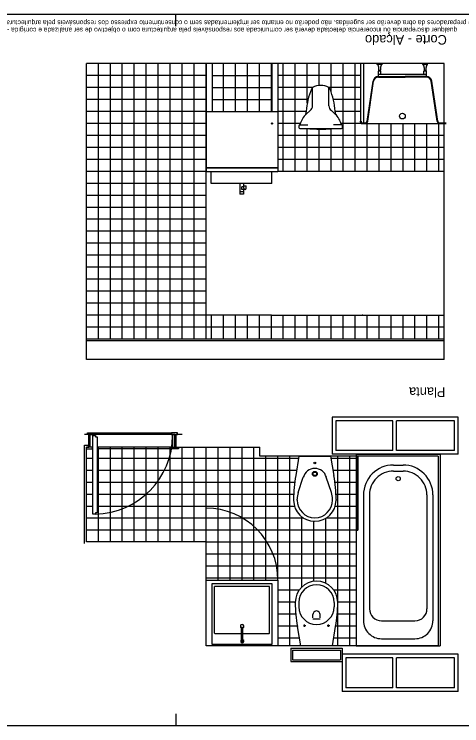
# Model space of a CAD drawing. Extents: x 1294.3 to 1305.9, y -284.7 to -278.8.
# Drawn here: x 1296.6 to 1300.34, y -284.72 to -278.78 of the extents above; entities that cross this region are included whole.
import ezdxf

# ---------------------------------------------------------------- set-up
doc = ezdxf.new("R2010")
doc.units = 0
for name, color, linetype in [('Level 1', 7, 'Continuous'), ('Level 10', 7, 'Continuous'), ('Level 11', 7, 'Continuous'), ('Level 13', 7, 'Continuous'), ('Level 2', 7, 'Continuous'), ('Level 36', 7, 'Continuous'), ('Level 4', 7, 'Continuous'), ('Level 60', 7, 'Continuous'), ('Level 62', 7, 'Continuous')]:
    doc.layers.add(name, color=color, linetype=linetype)

msp = doc.modelspace()

# ---------------------------------------------------------------- linework, layer by layer
at = {"layer": 'Level 1'}
for p, q in [((1297.206, -281.6585), (1297.206, -279.1885)), ((1300.196, -279.1885), (1297.206, -279.1885)), ((1299.496, -279.1885), (1299.496, -279.6685)), ((1299.521, -279.1885), (1299.521, -279.6835)), ((1300.196, -281.6585), (1300.196, -279.1885)), ((1299.496, -279.6685), (1299.501, -279.6685)), ((1299.501, -279.6685), (1299.501, -279.6735)), ((1299.511, -279.6835), (1299.521, -279.6835)), ((1300.196, -281.4885), (1297.206, -281.4885)), ((1300.196, -281.5035), (1297.206, -281.5035)), ((1300.196, -281.6585), (1297.206, -281.6585)), ((1300.311, -282.1396), (1299.2597, -282.1396)), ((1300.311, -282.4496), (1300.311, -282.1396)), ((1299.7653, -282.1696), (1299.2897, -282.1696)), ((1299.7653, -282.4196), (1299.7653, -282.1696)), ((1299.7953, -282.4196), (1299.7953, -282.1696)), ((1300.281, -282.1696), (1299.7953, -282.1696)), ((1300.281, -282.4196), (1300.281, -282.1696)), ((1297.226, -282.2846), (1297.191, -282.2846)), ((1297.226, -282.3896), (1297.226, -282.2846)), ((1298.006, -282.2846), (1297.956, -282.2846)), ((1297.956, -282.3896), (1297.956, -282.2846)), ((1297.191, -283.1946), (1297.191, -282.3746)), ((1297.191, -282.3746), (1297.226, -282.3746)), ((1297.206, -283.1796), (1297.206, -282.3896)), ((1297.206, -282.3896), (1297.226, -282.3896)), ((1297.956, -282.3896), (1298.656, -282.3896)), ((1298.656, -282.4646), (1298.656, -282.3896)), ((1299.7653, -282.4196), (1299.2897, -282.4196)), ((1300.281, -282.4196), (1299.7953, -282.4196)), ((1300.146, -282.4646), (1298.656, -282.4646)), ((1300.311, -282.4496), (1299.2597, -282.4496)), ((1300.311, -282.4496), (1299.2597, -282.4496)), ((1300.146, -282.4646), (1300.146, -284.0496)), ((1298.206, -283.1796), (1297.206, -283.1796)), ((1298.206, -284.0496), (1298.206, -283.1796)), ((1300.146, -284.0496), (1298.206, -284.0496)), ((1300.3122, -284.1196), (1299.3433, -284.1196)), ((1299.7665, -284.1496), (1299.3733, -284.1496)), ((1299.7665, -284.3996), (1299.7665, -284.1496)), ((1299.7965, -284.3996), (1299.7965, -284.1496)), ((1300.2822, -284.1496), (1299.7965, -284.1496)), ((1300.2822, -284.3996), (1300.2822, -284.1496)), ((1300.3122, -284.4296), (1300.3122, -284.1196)), ((1299.7665, -284.3996), (1299.3733, -284.3996)), ((1300.2822, -284.3996), (1299.7965, -284.3996)), ((1300.3122, -284.4296), (1299.3433, -284.4296))]:
    msp.add_line(p, q, dxfattribs=at)
for points in [[(1299.2597, -282.1396), (1299.2597, -282.4496)], [(1299.2897, -282.1696), (1299.2897, -282.4196)], [(1299.3433, -284.1196), (1299.3433, -284.4296)], [(1299.3733, -284.1496), (1299.3733, -284.3996)]]:
    msp.add_lwpolyline(points, dxfattribs=at)
msp.add_arc((1299.511, -279.6735), 0.01, 180, 270, dxfattribs=at)
at = {"layer": 'Level 10'}
for p, q in [((1297.306, -281.4885), (1297.306, -279.1885)), ((1297.406, -281.4885), (1297.406, -279.1885)), ((1297.506, -281.4885), (1297.506, -279.1885)), ((1297.606, -281.4885), (1297.606, -279.1885)), ((1297.706, -281.4885), (1297.706, -279.1885)), ((1297.806, -281.4885), (1297.806, -279.1885)), ((1297.906, -281.4885), (1297.906, -279.1885)), ((1298.006, -281.4885), (1298.006, -279.1885)), ((1298.106, -281.4885), (1298.106, -279.1885)), ((1298.351, -279.5885), (1298.351, -279.1885)), ((1298.451, -279.5885), (1298.451, -279.1885)), ((1298.551, -279.5885), (1298.551, -279.1885)), ((1298.651, -279.5885), (1298.651, -279.1885)), ((1298.751, -279.5885), (1298.751, -279.1885)), ((1298.806, -279.1885), (1298.806, -279.5885)), ((1298.851, -280.0885), (1298.851, -279.1885)), ((1298.951, -280.0885), (1298.951, -279.1885)), ((1299.051, -279.519), (1299.051, -279.1885)), ((1299.151, -279.3709), (1299.151, -279.1885)), ((1299.251, -279.4275), (1299.251, -279.1885)), ((1299.351, -280.0885), (1299.351, -279.1885)), ((1299.451, -280.0885), (1299.451, -279.1885)), ((1298.206, -279.2885), (1297.206, -279.2885)), ((1298.256, -279.2885), (1298.7558, -279.2885)), ((1299.496, -279.2885), (1298.8058, -279.2885)), ((1298.206, -279.3885), (1297.206, -279.3885)), ((1298.256, -279.3885), (1298.7558, -279.3885)), ((1299.0967, -279.3885), (1298.8058, -279.3885)), ((1299.496, -279.3885), (1299.2301, -279.3885)), ((1298.206, -279.4885), (1297.206, -279.4885)), ((1298.256, -279.4885), (1298.7558, -279.4885)), ((1299.0577, -279.4885), (1298.8058, -279.4885)), ((1299.496, -279.4885), (1299.2693, -279.4885)), ((1298.206, -279.5885), (1297.206, -279.5885)), ((1299.0415, -279.5885), (1298.8058, -279.5885)), ((1299.496, -279.5885), (1299.2856, -279.5885)), ((1298.206, -279.6885), (1297.206, -279.6885)), ((1298.9939, -279.6885), (1298.8058, -279.6885)), ((1299.506, -279.6885), (1299.3331, -279.6885)), ((1299.551, -280.0885), (1299.551, -279.6885)), ((1299.651, -280.0885), (1299.651, -279.6885)), ((1299.751, -280.0885), (1299.751, -279.6885)), ((1299.851, -280.0885), (1299.851, -279.6885)), ((1299.951, -280.0885), (1299.951, -279.6885)), ((1300.051, -280.0885), (1300.051, -279.6885)), ((1300.151, -280.0885), (1300.151, -279.6885)), ((1299.051, -280.0885), (1299.051, -279.7304)), ((1299.151, -280.0885), (1299.151, -279.7355)), ((1299.251, -280.0885), (1299.251, -279.7327)), ((1298.206, -279.7885), (1297.206, -279.7885)), ((1300.196, -279.7885), (1298.8058, -279.7885)), ((1298.206, -279.8885), (1297.206, -279.8885)), ((1300.196, -279.8885), (1298.8058, -279.8885)), ((1298.206, -279.9885), (1297.206, -279.9885)), ((1300.196, -279.9885), (1298.8058, -279.9885)), ((1298.206, -280.0885), (1297.206, -280.0885)), ((1298.206, -280.1885), (1297.206, -280.1885)), ((1298.206, -280.2885), (1297.206, -280.2885)), ((1298.206, -280.3885), (1297.206, -280.3885)), ((1298.206, -280.4885), (1297.206, -280.4885)), ((1298.206, -280.5885), (1297.206, -280.5885)), ((1298.206, -280.6885), (1297.206, -280.6885)), ((1298.206, -280.7885), (1297.206, -280.7885)), ((1298.206, -280.8885), (1297.206, -280.8885)), ((1298.206, -280.9885), (1297.206, -280.9885)), ((1298.206, -281.0885), (1297.206, -281.0885)), ((1298.206, -281.1885), (1297.206, -281.1885)), ((1298.206, -281.2885), (1297.206, -281.2885)), ((1298.251, -281.4885), (1298.251, -281.2885)), ((1298.351, -281.4885), (1298.351, -281.2885)), ((1298.451, -281.4885), (1298.451, -281.2885)), ((1298.551, -281.4885), (1298.551, -281.2885)), ((1298.651, -281.4885), (1298.651, -281.2885)), ((1298.751, -281.4885), (1298.751, -281.2885)), ((1298.751, -281.4885), (1298.751, -281.2885)), ((1298.851, -281.4885), (1298.851, -281.2885)), ((1298.951, -281.4885), (1298.951, -281.2885)), ((1299.051, -281.4885), (1299.051, -281.2885)), ((1299.151, -281.4885), (1299.151, -281.2885)), ((1299.251, -281.4885), (1299.251, -281.2885)), ((1299.351, -281.4885), (1299.351, -281.2885)), ((1299.451, -281.4885), (1299.451, -281.2885)), ((1299.551, -281.4885), (1299.551, -281.2885)), ((1299.651, -281.4885), (1299.651, -281.2885)), ((1299.751, -281.4885), (1299.751, -281.2885)), ((1299.851, -281.4885), (1299.851, -281.2885)), ((1299.951, -281.4885), (1299.951, -281.2885)), ((1300.051, -281.4885), (1300.051, -281.2885)), ((1300.151, -281.4885), (1300.151, -281.2885)), ((1300.196, -281.3885), (1297.206, -281.3885)), ((1297.916, -282.2846), (1297.266, -282.2846)), ((1297.926, -282.3896), (1297.296, -282.3896)), ((1297.306, -283.1796), (1297.306, -282.3896)), ((1297.406, -283.1796), (1297.406, -282.3896)), ((1297.506, -283.1796), (1297.506, -282.3896)), ((1297.606, -283.1796), (1297.606, -282.3896)), ((1297.706, -283.1796), (1297.706, -282.3896)), ((1297.806, -283.1796), (1297.806, -282.3896)), ((1297.906, -283.1796), (1297.906, -282.3896)), ((1298.006, -283.1796), (1298.006, -282.3896)), ((1298.106, -283.1796), (1298.106, -282.3896)), ((1298.206, -283.1796), (1298.206, -282.3896)), ((1298.306, -283.4996), (1298.306, -282.3896)), ((1298.406, -283.4996), (1298.406, -282.3896)), ((1298.506, -283.4996), (1298.506, -282.3896)), ((1298.606, -283.4996), (1298.606, -282.3896)), ((1297.261, -282.4846), (1297.206, -282.4846)), ((1298.9787, -282.4846), (1297.296, -282.4846)), ((1298.706, -283.4996), (1298.706, -282.4646)), ((1298.806, -283.4996), (1298.806, -282.4646)), ((1298.906, -284.0496), (1298.906, -282.4646)), ((1299.461, -282.4846), (1299.2499, -282.4846)), ((1299.306, -284.0496), (1299.306, -282.4646)), ((1299.406, -284.0496), (1299.406, -282.4646)), ((1297.261, -282.5846), (1297.206, -282.5846)), ((1298.9622, -282.5846), (1297.296, -282.5846)), ((1299.461, -282.5846), (1299.2663, -282.5846)), ((1297.261, -282.6846), (1297.206, -282.6846)), ((1298.9462, -282.6846), (1297.296, -282.6846)), ((1299.461, -282.6846), (1299.2824, -282.6846)), ((1297.261, -282.7846), (1297.206, -282.7846)), ((1298.9377, -282.7846), (1297.296, -282.7846)), ((1299.461, -282.7846), (1299.2909, -282.7846)), ((1297.261, -282.8846), (1297.206, -282.8846)), ((1298.9447, -282.8846), (1297.296, -282.8846)), ((1299.461, -282.8846), (1299.2838, -282.8846)), ((1299.006, -283.5586), (1299.006, -282.9727)), ((1299.0235, -282.9846), (1297.206, -282.9846)), ((1299.106, -283.511), (1299.106, -283.0094)), ((1299.461, -282.9846), (1299.2051, -282.9846)), ((1299.206, -283.5275), (1299.206, -282.9841)), ((1299.461, -283.0846), (1297.206, -283.0846)), ((1299.461, -283.1846), (1298.206, -283.1846)), ((1299.461, -283.2846), (1298.206, -283.2846)), ((1299.461, -283.3846), (1298.206, -283.3846)), ((1299.461, -283.4846), (1298.206, -283.4846)), ((1298.9851, -283.5846), (1298.806, -283.5846)), ((1299.461, -283.5846), (1299.2732, -283.5846)), ((1298.9508, -283.6846), (1298.806, -283.6846)), ((1299.461, -283.6846), (1299.3058, -283.6846)), ((1298.955, -283.7846), (1298.806, -283.7846)), ((1299.461, -283.7846), (1299.3016, -283.7846)), ((1298.9688, -283.8846), (1298.806, -283.8846)), ((1299.461, -283.8846), (1299.2878, -283.8846)), ((1298.9853, -283.9846), (1298.806, -283.9846)), ((1299.461, -283.9846), (1299.2713, -283.9846))]:
    msp.add_line(p, q, dxfattribs=at)
at = {"layer": 'Level 11'}
for p, q in [((1299.6765, -279.1884), (1299.6352, -279.1884)), ((1299.6352, -279.1951), (1299.6352, -279.1884)), ((1299.6765, -279.1951), (1299.6352, -279.1951)), ((1299.6765, -279.1951), (1299.6765, -279.1884)), ((1300.0567, -279.1884), (1300.0154, -279.1884)), ((1300.0154, -279.1951), (1300.0154, -279.1884)), ((1300.0567, -279.1951), (1300.0154, -279.1951)), ((1300.0567, -279.1951), (1300.0567, -279.1884)), ((1299.6454, -279.252), (1299.6503, -279.246)), ((1299.6664, -279.252), (1299.6454, -279.252)), ((1299.6454, -279.2965), (1299.6454, -279.252)), ((1300.0466, -279.2784), (1299.6454, -279.2784)), ((1299.6454, -279.2965), (1299.8217, -279.2965)), ((1299.6615, -279.246), (1299.6503, -279.246)), ((1299.6664, -279.252), (1299.6615, -279.246)), ((1299.6664, -279.2784), (1299.6664, -279.252)), ((1299.8217, -279.2965), (1299.8702, -279.2965)), ((1300.0466, -279.2965), (1299.8702, -279.2965)), ((1300.0256, -279.252), (1300.0305, -279.246)), ((1300.0466, -279.252), (1300.0256, -279.252)), ((1300.0256, -279.2784), (1300.0256, -279.252)), ((1300.0417, -279.246), (1300.0305, -279.246)), ((1300.0466, -279.252), (1300.0417, -279.246)), ((1300.0466, -279.2784), (1300.0466, -279.252)), ((1300.0466, -279.3012), (1300.0466, -279.2784)), ((1299.5509, -279.6707), (1299.6009, -279.3349)), ((1299.5561, -279.6701), (1299.6058, -279.3356)), ((1299.6454, -279.3015), (1299.8217, -279.3015)), ((1299.8217, -279.3015), (1299.8702, -279.3015)), ((1300.0466, -279.3015), (1299.8702, -279.3015)), ((1300.1361, -279.6701), (1300.0862, -279.3356)), ((1300.141, -279.6694), (1300.0911, -279.3348)), ((1299.096, -279.5404), (1299.096, -279.389)), ((1299.231, -279.5404), (1299.231, -279.389)), ((1299.0418, -279.5857), (1299.0375, -279.6144)), ((1299.0418, -279.6104), (1299.0746, -279.5802)), ((1299.2852, -279.6104), (1299.2524, -279.5802)), ((1299.2895, -279.6144), (1299.2852, -279.5857)), ((1298.981, -279.7078), (1298.981, -279.7224)), ((1298.9868, -279.7001), (1299.0561, -279.7001)), ((1299.3402, -279.7001), (1299.2709, -279.7001)), ((1299.346, -279.7224), (1299.346, -279.7078)), ((1299.496, -279.6685), (1299.501, -279.6685)), ((1299.496, -279.6785), (1299.496, -279.6685)), ((1299.501, -279.6785), (1299.501, -279.6685)), ((1299.506, -279.6835), (1299.5361, -279.6835)), ((1299.506, -279.6885), (1299.5361, -279.6885)), ((1299.5359, -279.6885), (1300.156, -279.6885)), ((1300.156, -279.6835), (1300.211, -279.6835)), ((1300.156, -279.6885), (1300.211, -279.6885)), ((1298.2494, -280.1885), (1298.2494, -280.0885)), ((1298.7538, -280.1885), (1298.7538, -280.0885)), ((1298.4889, -280.1885), (1298.4889, -280.2785)), ((1298.5189, -280.1885), (1298.5189, -280.2185)), ((1298.4889, -280.2385), (1298.4889, -280.2785)), ((1298.5189, -280.2385), (1298.5189, -280.2785)), ((1298.5215, -280.2285), (1298.5215, -280.2085)), ((1298.5215, -280.2085), (1298.5415, -280.2085)), ((1298.5415, -280.2285), (1298.5415, -280.2085)), ((1298.5189, -280.2585), (1298.4889, -280.2585)), ((1298.5189, -280.2785), (1298.4889, -280.2785)), ((1298.982, -282.4646), (1298.9553, -282.6266)), ((1298.982, -282.4646), (1299.2466, -282.4646)), ((1299.2466, -282.4646), (1299.2732, -282.6266)), ((1299.461, -282.4496), (1299.461, -284.0496)), ((1299.461, -282.4496), (1300.161, -282.4496)), ((1300.161, -282.4496), (1300.161, -284.0496)), ((1299.771, -282.5396), (1299.851, -282.5396)), ((1299.771, -282.5896), (1299.851, -282.5896)), ((1298.9745, -282.7691), (1299.0181, -282.6411)), ((1299.2541, -282.7691), (1299.2104, -282.6411)), ((1299.521, -282.7896), (1299.521, -283.8396)), ((1299.571, -282.7896), (1299.571, -283.7396)), ((1300.051, -282.7896), (1300.051, -283.7396)), ((1300.101, -282.7896), (1300.101, -283.8396)), ((1298.9368, -282.8287), (1298.9368, -282.8324)), ((1298.9668, -282.8321), (1298.9668, -282.824)), ((1299.2618, -282.8321), (1299.2618, -282.824)), ((1299.2918, -282.8287), (1299.2918, -282.8324)), ((1298.2537, -283.5314), (1298.2537, -284.0306)), ((1298.7581, -283.5314), (1298.2537, -283.5314)), ((1298.2748, -283.941), (1298.2748, -283.5525)), ((1298.737, -283.5525), (1298.2748, -283.5525)), ((1298.737, -283.941), (1298.737, -283.5525)), ((1298.7581, -284.0306), (1298.7581, -283.5314)), ((1298.9508, -283.6904), (1298.9508, -283.6868)), ((1298.9808, -283.6871), (1298.9808, -283.7232)), ((1299.2758, -283.6871), (1299.2758, -283.7232)), ((1299.3058, -283.6904), (1299.3058, -283.6868)), ((1299.0983, -283.8151), (1299.0983, -283.7878)), ((1299.1583, -283.8151), (1299.1583, -283.7879)), ((1299.0283, -283.8914), (1299.0283, -283.8714)), ((1299.1583, -283.8274), (1299.0983, -283.8274)), ((1299.2283, -283.8914), (1299.2283, -283.8714)), ((1299.671, -283.8396), (1299.951, -283.8396)), ((1298.5019, -284.0098), (1298.5019, -283.9003)), ((1298.5132, -284.0098), (1298.5132, -283.9003)), ((1298.996, -284.0496), (1298.9693, -283.8875)), ((1299.0383, -283.8814), (1299.0183, -283.8814)), ((1299.2383, -283.8814), (1299.2183, -283.8814)), ((1299.2606, -284.0496), (1299.2873, -283.8875)), ((1298.2791, -283.9454), (1298.5019, -283.9454)), ((1298.5132, -283.9454), (1298.7326, -283.9454)), ((1299.671, -283.9896), (1299.951, -283.9896)), ((1298.2581, -284.035), (1298.7537, -284.035)), ((1299.2606, -284.0496), (1298.996, -284.0496)), ((1299.461, -284.0496), (1300.161, -284.0496)), ((1298.9133, -284.0696), (1298.9133, -284.1796)), ((1298.9133, -284.0696), (1299.3433, -284.0696)), ((1298.9283, -284.0846), (1299.3283, -284.0846)), ((1298.9283, -284.0846), (1298.9283, -284.1646)), ((1299.3283, -284.0846), (1299.3283, -284.1646)), ((1299.3433, -284.0696), (1299.3433, -284.1796)), ((1298.9283, -284.1646), (1299.3283, -284.1646)), ((1298.9133, -284.1796), (1299.3433, -284.1796))]:
    msp.add_line(p, q, dxfattribs=at)
msp.add_lwpolyline([(1298.989, -279.7304), (1299.166, -279.7304), (1299.338, -279.7304)], dxfattribs=at)
for centre, radius in [((1299.846, -279.6265), 0.0242), ((1299.1143, -282.5226), 0.00766), ((1299.1143, -282.6134), 0.02), ((1299.1143, -282.6134), 0.0146), ((1299.811, -282.654), 0.0173)]:
    msp.add_circle(centre, radius, dxfattribs=at)
for centre, radius, start, end in [((1299.6288, -279.2122), 0.0182, 10.7191, 69.4889), ((1299.4505, -279.246), 0.1997, 0, 10.7193), ((1299.8612, -279.246), 0.1997, 169.2806, 180), ((1299.6829, -279.2122), 0.0182, 110.5106, 169.2809), ((1300.009, -279.2122), 0.0182, 10.7191, 69.4889), ((1299.8307, -279.246), 0.1997, 0, 10.7193), ((1300.2414, -279.246), 0.1997, 169.2806, 180), ((1300.0631, -279.2122), 0.0182, 110.5106, 169.2809), ((1299.6454, -279.3415), 0.045, 89.99999, 171.54027), ((1300.0466, -279.3415), 0.045, 8.48205, 90.00033), ((1299.6454, -279.3415), 0.04, 89.9998, 171.53996), ((1300.0466, -279.3415), 0.04, 8.48232, 89.99979), ((1299.6654, -279.6379), 0.6258, 157.87828, 175.22161), ((1299.1164, -279.4157), 0.0336, 127.37509, 156.36146), ((1299.1635, -279.5015), 0.1312, 59.05228, 120.94772), ((1299.2105, -279.4157), 0.0336, 23.63854, 52.62491), ((1298.6615, -279.6379), 0.6258, 4.77839, 22.12172), ((1299.0444, -279.5383), 0.0516, 305.66936, 357.68937), ((1299.2825, -279.5383), 0.0516, 182.31063, 234.33064), ((1299.1555, -279.7338), 0.1678, 132.66339, 166.38286), ((1299.1715, -279.7338), 0.1678, 13.61714, 47.33661), ((1298.989, -279.7078), 0.008, 106.01353, 180), ((1298.9846, -279.6924), 0.008, 286.01353, 346.38286), ((1299.3423, -279.6924), 0.008, 193.61714, 253.98647), ((1299.3379, -279.7078), 0.008, 0, 73.98647), ((1299.506, -279.6785), 0.01, 179.99918, 270.00122), ((1299.506, -279.6785), 0.005, 180.0041, 270.00021), ((1299.5361, -279.6685), 0.02, 269.99959, 355.23718), ((1299.5361, -279.6685), 0.015, 270.00084, 351.54079), ((1300.156, -279.6685), 0.02, 184.76377, 270.00052), ((1300.156, -279.6685), 0.015, 184.76377, 270.00052), ((1298.989, -279.7224), 0.008, 180, 270), ((1299.171, -278.1599), 1.5757, 265.34686, 269.63229), ((1299.1569, -278.1757), 1.5598, 270.14847, 274.66453), ((1299.3379, -279.7224), 0.008, 270, 0), ((1298.5315, -280.2285), 0.01, 180, 0), ((1299.771, -282.7896), 0.25, 89.99986, 179.99993), ((1299.851, -282.7896), 0.25, 359.99999, 90.0001), ((1299.1143, -282.6686), 0.1, 15.93166, 164.19529), ((1299.771, -282.7896), 0.2, 89.99997, 180.00001), ((1299.851, -282.7896), 0.2, 359.99997, 90.00002), ((1299.1668, -282.824), 0.2, 164.06928, 180.00056), ((1299.0618, -282.824), 0.2, 0.00165, 15.93186), ((1299.1143, -282.8321), 0.1775, 180.00018, 359.99986), ((1299.1143, -282.8321), 0.1475, 180.00018, 359.99986), ((1299.1283, -283.6871), 0.1775, 0.00023, 179.99991), ((1299.1283, -283.6871), 0.1475, 0.00023, 179.99991), ((1299.1283, -283.7232), 0.1475, 180.00018, 359.99986), ((1299.671, -283.7396), 0.1, 179.99997, 270.00005), ((1299.951, -283.7396), 0.1, 270.00014, 359.99987), ((1299.1283, -283.788), 0.03, 359.99953, 180.00125), ((1298.5072, -283.8859), 0.015, 293.63069, 249.28331), ((1299.671, -283.8396), 0.15, 179.99996, 269.99999), ((1299.951, -283.8396), 0.15, 269.9999, 0.00017), ((1298.5076, -283.8997), 0.00566, 354.01756, 185.9962), ((1298.2791, -283.941), 0.00438, 180, 270), ((1298.7326, -283.941), 0.00438, 270, 0), ((1298.2581, -284.0306), 0.00438, 180, 270), ((1298.508, -284.0104), 0.0135, 116.71993, 67.39087), ((1298.5076, -284.0104), 0.00566, 174.0038, 5.98244), ((1298.7537, -284.0306), 0.00438, 270, 0)]:
    msp.add_arc(centre, radius, start, end, dxfattribs=at)
for centre, major_axis, ratio, start_param, end_param in [((1300.3368, -282.8287), (-1.4, 0), 0.88995, 6.120269, 6.283187), ((1297.8918, -282.8287), (1.4, 0), 0.88995, 6.283183, 6.446102), ((1300.3508, -283.6905), (-1.4, 0), 0.867931, 6.283184, 6.446103), ((1297.9058, -283.6905), (1.4, 0), 0.867931, 6.120269, 6.283188)]:
    msp.add_ellipse(centre, major_axis=major_axis, ratio=ratio, start_param=start_param, end_param=end_param, dxfattribs=at)
at = {"layer": 'Level 13'}
for p, q in [((1298.206, -279.1885), (1298.206, -280.0885)), ((1298.256, -279.1885), (1298.256, -279.5885)), ((1298.7558, -279.1885), (1298.7558, -279.5885)), ((1298.8058, -279.1885), (1298.8058, -280.0885)), ((1298.206, -279.5885), (1298.8058, -279.5885)), ((1298.206, -280.0565), (1298.8058, -280.0565)), ((1298.206, -280.0585), (1298.8058, -280.0585)), ((1298.206, -280.0885), (1298.8058, -280.0885)), ((1298.7538, -280.1885), (1298.2494, -280.1885)), ((1297.216, -282.2696), (1297.266, -282.2696)), ((1297.216, -282.2846), (1297.216, -282.2696)), ((1297.266, -282.2846), (1297.216, -282.2846)), ((1297.236, -282.3896), (1297.236, -282.2846)), ((1297.236, -282.2846), (1297.266, -282.2846)), ((1297.256, -282.2846), (1297.256, -282.3896)), ((1297.261, -282.9489), (1297.261, -282.2939)), ((1297.261, -282.2939), (1297.281, -282.2939)), ((1297.266, -282.2696), (1297.266, -282.2846)), ((1297.281, -282.2939), (1297.281, -282.3039)), ((1297.281, -282.3039), (1297.296, -282.3039)), ((1297.296, -282.3039), (1297.296, -282.9389)), ((1297.966, -282.2696), (1297.916, -282.2696)), ((1297.916, -282.2696), (1297.916, -282.2846)), ((1297.946, -282.2846), (1297.916, -282.2846)), ((1297.916, -282.2846), (1297.966, -282.2846)), ((1297.926, -282.2846), (1297.926, -282.3896)), ((1297.946, -282.3896), (1297.946, -282.2846)), ((1297.966, -282.2846), (1297.966, -282.2696)), ((1297.256, -282.3896), (1297.206, -282.3896)), ((1297.206, -282.4046), (1297.256, -282.4046)), ((1297.256, -282.3896), (1297.236, -282.3896)), ((1297.256, -282.4046), (1297.256, -282.3896)), ((1297.926, -282.4046), (1297.926, -282.3896)), ((1297.926, -282.3896), (1297.946, -282.3896)), ((1297.926, -282.3896), (1297.976, -282.3896)), ((1297.976, -282.4046), (1297.926, -282.4046)), ((1297.976, -282.3896), (1297.976, -282.4046)), ((1297.281, -282.9489), (1297.261, -282.9489)), ((1297.281, -282.9389), (1297.281, -282.9486)), ((1297.296, -282.9389), (1297.281, -282.9389))]:
    msp.add_line(p, q, dxfattribs=at)
msp.add_circle((1298.7558, -279.6885), 0.005, dxfattribs=at)
at = {"layer": 'Level 2'}
for p, q in [((1298.206, -281.4885), (1298.206, -279.1885)), ((1300.196, -280.0885), (1298.8058, -280.0885)), ((1298.5039, -280.2385), (1298.5039, -280.2185)), ((1298.5215, -280.2185), (1298.5039, -280.2185)), ((1298.5315, -280.2385), (1298.5039, -280.2385)), ((1298.751, -281.2885), (1298.206, -281.2885)), ((1298.751, -281.2885), (1300.196, -281.2885)), ((1298.206, -283.4996), (1298.806, -283.4996)), ((1298.206, -284.0496), (1298.206, -283.4996)), ((1298.806, -283.4996), (1298.806, -284.0496))]:
    msp.add_line(p, q, dxfattribs=at)
at = {"layer": 'Level 36'}
for p, q in [((1299.514, -281.2885), (1299.509, -281.2885)), ((1299.469, -282.4646), (1299.469, -283.0846)), ((1299.474, -282.4646), (1299.474, -283.0846)), ((1299.469, -283.0846), (1299.474, -283.0846))]:
    msp.add_line(p, q, dxfattribs=at)
at = {"layer": 'Level 4'}
for p, q in [((1297.266, -282.2696), (1297.916, -282.2696)), ((1297.926, -282.4046), (1297.296, -282.4046)), ((1298.206, -283.1796), (1298.206, -282.8996))]:
    msp.add_line(p, q, dxfattribs=at)
msp.add_arc((1298.206, -283.4996), 0.6, 0, 90, dxfattribs=at)
msp.add_ellipse((1297.2673, -282.2939), major_axis=(-0.6586, 0), ratio=0.994279, start_param=1.591512, end_param=3.141593, dxfattribs=at)
at = {"layer": 'Level 62'}
for p, q in [((1297.9525, -278.8763), (1297.9525, -278.7763)), ((1297.9525, -284.6163), (1297.9525, -284.7163))]:
    msp.add_line(p, q, dxfattribs=at)
msp.add_lwpolyline([(1305.8521, -278.7763), (1305.8521, -284.7163), (1294.2525, -284.7163), (1294.2525, -278.7763)], close=True, dxfattribs=at)

# ---------------------------------------------------------------- texts
at = {"layer": 'Level 60'}
for s, p in [('Corte - Alçado', (1300.2173, -278.9498)), ('Planta', (1300.205, -281.8919))]:
    msp.add_text(s, height=0.08, rotation=180.00001, dxfattribs=at).set_placement(p)
at = {"layer": 'Level 62'}
for s, p in [('cutantes e preparadores da obra deverão ser sugeridas. não poderão no entanto ser implementadas sem o consentimento expresso dos responsáveis pela arquitectura', (1300.6504, -278.8283)), ('qualquer discrepancia ou incoerencia detectada deverá ser comunicada aos responsáveis pela arquitectura com o objectivo de ser analizada e corrigida -', (1300.3038, -278.8893))]:
    msp.add_text(s, height=0.0399996, rotation=180, dxfattribs=at).set_placement(p)

doc.saveas('drawing.dxf')
